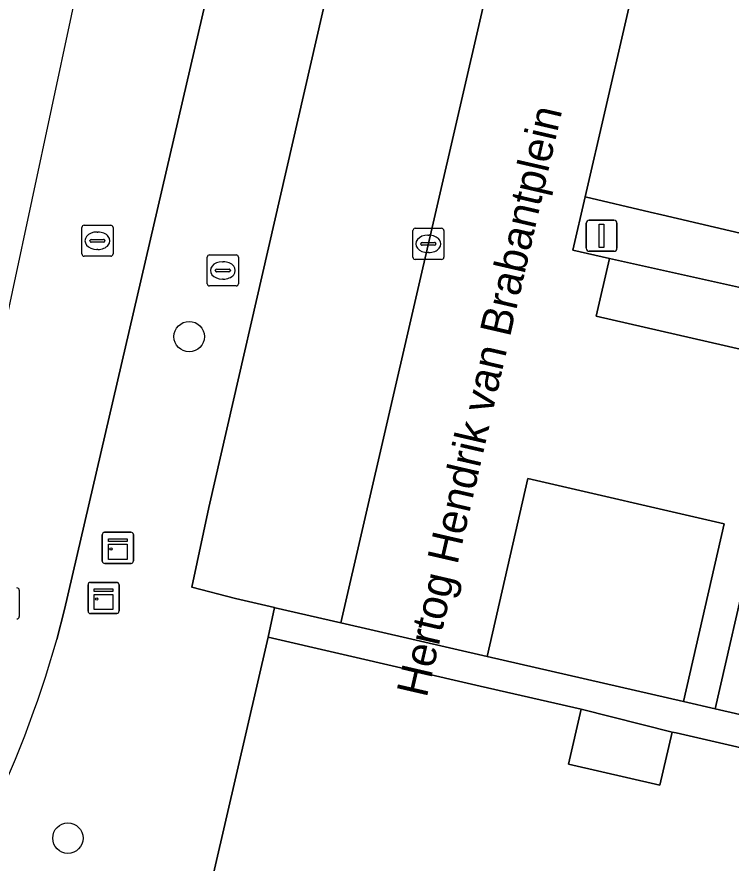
# Model space of a CAD drawing. Extents: x 161798 to 162385, y 382315 to 382833.
# Drawn here: x 161846.34 to 161869.31, y 382603.74 to 382630.93 of the extents above; entities that cross this region are included whole.
import ezdxf

# ---------------------------------------------------------------- set-up
doc = ezdxf.new("R2010")
doc.units = 0
for name, color, linetype in [('IMGEO_Boom', 7, 'Continuous'), ('IMGEO_Groenvoorziening', 7, 'Continuous'), ('IMGEO_Kast', 7, 'Continuous'), ('IMGEO_Kolk', 7, 'Continuous'), ('IMGEO_Lichtmast', 7, 'Continuous'), ('IMGEO_Openbare_ruimte_label', 7, 'Continuous'), ('IMGEO_Pand', 7, 'Continuous'), ('IMGEO_Parkeervlak_open', 7, 'Continuous'), ('IMGEO_Rijbaan_lokaal_gesloten', 7, 'Continuous'), ('IMGEO_Rijbaan_lokaal_open', 7, 'Continuous'), ('IMGEO_Rioolput', 7, 'Continuous'), ('IMGEO_Voetpad_open', 7, 'Continuous')]:
    doc.layers.add(name, color=color, linetype=linetype)

msp = doc.modelspace()

# ---------------------------------------------------------------- linework, layer by layer
at = {"layer": 'IMGEO_Boom'}
for centre in [(161851.88, 382620.655), (161847.979, 382604.538)]:
    msp.add_circle(centre, 0.489, dxfattribs=at)
at = {"layer": 'IMGEO_Groenvoorziening'}
msp.add_lwpolyline([(161866.576, 382633.64), (161864.615, 382625.149), (161866.712, 382624.656), (161867.078, 382624.57), (161873.854, 382622.982), (161875.823, 382622.52), (161880.4, 382621.447)], dxfattribs=at)
at = {"layer": 'IMGEO_Kast'}
for p, q in [((161849.086, 382613.443), (161849.086, 382614.284)), ((161849.086, 382614.284), (161849.086, 382613.443)), ((161849.161, 382614.368), (161850.002, 382614.368)), ((161850.002, 382614.368), (161849.161, 382614.368)), ((161850.086, 382614.293), (161850.086, 382613.452)), ((161850.086, 382613.452), (161850.086, 382614.293)), ((161850.011, 382613.368), (161849.17, 382613.368)), ((161849.17, 382613.368), (161850.011, 382613.368)), ((161848.626, 382611.833), (161848.626, 382612.674)), ((161848.626, 382612.674), (161848.626, 382611.833)), ((161848.701, 382612.758), (161849.542, 382612.758)), ((161849.542, 382612.758), (161848.701, 382612.758)), ((161849.626, 382612.683), (161849.626, 382611.842)), ((161849.626, 382611.842), (161849.626, 382612.683)), ((161849.551, 382611.758), (161848.71, 382611.758)), ((161848.71, 382611.758), (161849.551, 382611.758))]:
    msp.add_line(p, q, dxfattribs=at)
for points in [[(161849.281, 382614.158), (161849.881, 382614.158), (161849.881, 382614.073), (161849.281, 382614.073), (161849.281, 382614.158)], [(161849.281, 382613.983), (161849.881, 382613.983), (161849.881, 382613.494), (161849.281, 382613.494), (161849.281, 382613.983)], [(161848.821, 382612.548), (161849.421, 382612.548), (161849.421, 382612.463), (161848.821, 382612.463), (161848.821, 382612.548)], [(161848.821, 382612.373), (161849.421, 382612.373), (161849.421, 382611.884), (161848.821, 382611.884), (161848.821, 382612.373)]]:
    msp.add_lwpolyline(points, dxfattribs=at)
for centre in [(161849.365, 382613.832), (161848.905, 382612.222)]:
    msp.add_circle(centre, 0.0377, dxfattribs=at)
for centre, start, end in [((161849.164, 382614.29), 92.4484, 184.2845), ((161849.164, 382614.29), 92.4484, 184.2845), ((161850.008, 382614.29), 2.4484, 94.2845), ((161850.008, 382614.29), 2.4484, 94.2845), ((161849.164, 382613.446), 182.4484, 274.2845), ((161849.164, 382613.446), 182.4484, 274.2845), ((161850.008, 382613.446), 272.4484, 4.2845), ((161850.008, 382613.446), 272.4484, 4.2845), ((161848.704, 382612.68), 92.4484, 184.2845), ((161848.704, 382612.68), 92.4484, 184.2845), ((161849.548, 382612.68), 2.4484, 94.2845), ((161849.548, 382612.68), 2.4484, 94.2845), ((161848.704, 382611.836), 182.4484, 274.2845), ((161848.704, 382611.836), 182.4484, 274.2845), ((161849.548, 382611.836), 272.4484, 4.2845), ((161849.548, 382611.836), 272.4484, 4.2845)]:
    msp.add_arc(centre, 0.0779, start, end, dxfattribs=at)
at = {"layer": 'IMGEO_Kolk'}
for p, q in [((161859.072, 382623.21), (161859.072, 382624.062)), ((161859.147, 382624.136), (161859.999, 382624.136)), ((161860.073, 382624.062), (161860.073, 382623.21)), ((161859.56, 382623.916), (161859.585, 382623.916)), ((161859.331, 382623.63), (161859.331, 382623.642)), ((161859.769, 382623.593), (161859.371, 382623.593)), ((161859.374, 382623.679), (161859.772, 382623.679)), ((161859.815, 382623.642), (161859.815, 382623.63)), ((161859.583, 382623.356), (161859.558, 382623.356)), ((161859.999, 382623.136), (161859.147, 382623.136))]:
    msp.add_line(p, q, dxfattribs=at)
for points in [[(161859.072, 382623.21), (161859.072, 382624.062)], [(161859.147, 382624.136), (161859.999, 382624.136)], [(161860.073, 382624.062), (161860.073, 382623.21)], [(161859.999, 382623.136), (161859.147, 382623.136)]]:
    msp.add_lwpolyline(points, dxfattribs=at)
for centre, radius, start, end in [((161859.149, 382624.06), 0.0765, 91.552, 178.448), ((161859.149, 382624.06), 0.0765, 91.552, 178.448), ((161859.997, 382624.06), 0.0765, 1.552, 88.448), ((161859.997, 382624.06), 0.0765, 1.552, 88.448), ((161859.371, 382623.639), 0.0403, 85.8775, 175.7526), ((161859.368, 382623.629), 0.0366, 178.938, 274.7102), ((161859.772, 382623.636), 0.043, 264.8664, 352.4533), ((161859.776, 382623.641), 0.0386, 1.7309, 96.639), ((161859.149, 382623.212), 0.0765, 181.552, 268.448), ((161859.149, 382623.212), 0.0765, 181.552, 268.448), ((161859.997, 382623.212), 0.0765, 271.552, 358.448), ((161859.997, 382623.212), 0.0765, 271.552, 358.448)]:
    msp.add_arc(centre, radius, start, end, dxfattribs=at)
for centre, major_axis, ratio, start_param, end_param in [((161859.559, 382623.636), (-0.387, 0.002), 0.722429, 4.712389, 7.853982), ((161859.584, 382623.636), (-0.39, 0.002), 0.717154, 1.570796, 4.712389)]:
    msp.add_ellipse(centre, major_axis=major_axis, ratio=ratio, start_param=start_param, end_param=end_param, dxfattribs=at)
at = {"layer": 'IMGEO_Lichtmast'}
for p, q in [((161864.649, 382623.499), (161864.649, 382624.299)), ((161864.649, 382624.299), (161864.649, 382623.499)), ((161864.749, 382624.399), (161865.539, 382624.399)), ((161865.539, 382624.399), (161864.749, 382624.399)), ((161865.639, 382624.299), (161865.639, 382623.499)), ((161865.639, 382623.499), (161865.639, 382624.299)), ((161865.539, 382623.399), (161864.749, 382623.399)), ((161864.749, 382623.399), (161865.539, 382623.399))]:
    msp.add_line(p, q, dxfattribs=at)
msp.add_lwpolyline([(161865.069, 382624.274), (161865.219, 382624.274), (161865.219, 382623.524), (161865.069, 382623.524), (161865.069, 382624.274)], dxfattribs=at)
for centre, start, end in [((161864.749, 382624.299), 90, 180), ((161864.749, 382624.299), 90, 180), ((161865.539, 382624.299), 0, 90), ((161865.539, 382624.299), 360, 90), ((161864.749, 382623.499), 180, 270), ((161864.749, 382623.499), 180, 270), ((161865.539, 382623.499), 270, 0), ((161865.539, 382623.499), 270, 0)]:
    msp.add_arc(centre, 0.1, start, end, dxfattribs=at)
at = {"layer": 'IMGEO_Pand'}
msp.add_lwpolyline([(161880.75, 382604.884), (161878.792, 382605.334), (161867.541, 382607.918), (161867.413, 382607.947), (161867.021, 382606.239), (161864.082, 382606.914), (161864.488, 382608.68), (161861.243, 382609.426), (161854.417, 382610.994), (161848.273, 382584.466), (161874.618, 382578.415), (161876.31, 382585.719), (161876.316, 382585.744)], close=True, dxfattribs=at)
at = {"layer": 'IMGEO_Parkeervlak_open'}
for points in [[(161867.395, 382657.47), (161867.403, 382657.512), (161862.499, 382658.624), (161852.515, 382615.16), (161851.961, 382612.607), (161853.365, 382612.238), (161854.625, 382611.948), (161854.643, 382611.944), (161856.759, 382611.458)], [(161865.4, 382623.168), (161864.975, 382621.309), (161881.719, 382617.477), (161882.157, 382619.325), (161873.025, 382621.478)], [(161880.256, 382611.317), (161869.944, 382613.686), (161868.797, 382608.696), (161879.024, 382606.347)]]:
    msp.add_lwpolyline(points, close=True, dxfattribs=at)
at = {"layer": 'IMGEO_Rijbaan_lokaal_gesloten'}
msp.add_lwpolyline([(161847.621, 382610.917), (161847.865, 382611.889), (161858.977, 382659.682), (161854.413, 382660.541), (161842.384, 382604.352), (161834.027, 382596.507)], dxfattribs=at)
msp.add_arc((161812.716, 382620.857), 36.292, 323.5737, 344.1044, dxfattribs=at)
at = {"layer": 'IMGEO_Rijbaan_lokaal_open'}
msp.add_lwpolyline([(161864.975, 382621.309), (161865.4, 382623.168), (161864.218, 382623.43), (161864.615, 382625.149), (161866.576, 382633.64), (161871.857, 382656.486), (161867.395, 382657.47), (161856.759, 382611.458), (161861.462, 382610.378), (161862.775, 382616.091), (161869.085, 382614.642), (161867.774, 382608.931), (161868.797, 382608.696), (161869.944, 382613.686), (161880.256, 382611.317), (161880.309, 382611.531), (161881.719, 382617.477)], close=True, dxfattribs=at)
at = {"layer": 'IMGEO_Rioolput'}
for p, q in [((161848.504, 382624.237), (161849.356, 382624.237)), ((161848.429, 382623.311), (161848.429, 382624.163)), ((161848.917, 382624.017), (161848.942, 382624.017)), ((161849.43, 382624.163), (161849.43, 382623.311)), ((161848.688, 382623.731), (161848.688, 382623.743)), ((161849.126, 382623.694), (161848.728, 382623.694)), ((161848.731, 382623.78), (161849.129, 382623.78)), ((161849.172, 382623.743), (161849.172, 382623.731)), ((161848.94, 382623.457), (161848.915, 382623.457)), ((161849.356, 382623.237), (161848.504, 382623.237)), ((161852.462, 382622.357), (161852.462, 382623.209)), ((161852.537, 382623.283), (161853.389, 382623.283)), ((161853.463, 382623.209), (161853.463, 382622.357)), ((161852.95, 382623.063), (161852.975, 382623.063)), ((161852.721, 382622.777), (161852.721, 382622.789)), ((161853.159, 382622.74), (161852.761, 382622.74)), ((161852.764, 382622.826), (161853.162, 382622.826)), ((161853.205, 382622.789), (161853.205, 382622.777)), ((161852.973, 382622.503), (161852.948, 382622.503)), ((161853.389, 382622.283), (161852.537, 382622.283)), ((161846.413, 382612.508), (161846.413, 382611.656))]:
    msp.add_line(p, q, dxfattribs=at)
for points in [[(161848.504, 382624.237), (161849.356, 382624.237)], [(161848.429, 382623.311), (161848.429, 382624.163)], [(161849.43, 382624.163), (161849.43, 382623.311)], [(161849.356, 382623.237), (161848.504, 382623.237)], [(161852.462, 382622.357), (161852.462, 382623.209)], [(161852.537, 382623.283), (161853.389, 382623.283)], [(161853.463, 382623.209), (161853.463, 382622.357)], [(161853.389, 382622.283), (161852.537, 382622.283)], [(161846.413, 382612.508), (161846.413, 382611.656)]]:
    msp.add_lwpolyline(points, dxfattribs=at)
for centre, radius, start, end in [((161848.506, 382624.161), 0.0765, 91.552, 178.448), ((161848.506, 382624.161), 0.0765, 91.552, 178.448), ((161849.354, 382624.161), 0.0765, 1.552, 88.448), ((161849.354, 382624.161), 0.0765, 1.552, 88.448), ((161848.728, 382623.74), 0.0403, 85.8775, 175.7526), ((161848.725, 382623.73), 0.0366, 178.938, 274.7102), ((161849.129, 382623.737), 0.043, 264.8664, 352.4533), ((161849.133, 382623.742), 0.0386, 1.7309, 96.639), ((161848.506, 382623.313), 0.0765, 181.552, 268.448), ((161848.506, 382623.313), 0.0765, 181.552, 268.448), ((161849.354, 382623.313), 0.0765, 271.552, 358.448), ((161849.354, 382623.313), 0.0765, 271.552, 358.448), ((161852.539, 382623.207), 0.0765, 91.552, 178.448), ((161852.539, 382623.207), 0.0765, 91.552, 178.448), ((161853.387, 382623.207), 0.0765, 1.552, 88.448), ((161853.387, 382623.207), 0.0765, 1.552, 88.448), ((161852.761, 382622.786), 0.0403, 85.8775, 175.7526), ((161852.758, 382622.776), 0.0366, 178.938, 274.7102), ((161853.162, 382622.783), 0.043, 264.8664, 352.4533), ((161853.166, 382622.788), 0.0386, 1.7309, 96.639), ((161852.539, 382622.359), 0.0765, 181.552, 268.448), ((161852.539, 382622.359), 0.0765, 181.552, 268.448), ((161853.387, 382622.359), 0.0765, 271.552, 358.448), ((161853.387, 382622.359), 0.0765, 271.552, 358.448), ((161846.337, 382612.506), 0.0765, 1.552, 88.448), ((161846.337, 382612.506), 0.0765, 1.552, 88.448), ((161846.337, 382611.658), 0.0765, 271.552, 358.448), ((161846.337, 382611.658), 0.0765, 271.552, 358.448)]:
    msp.add_arc(centre, radius, start, end, dxfattribs=at)
for centre, major_axis, ratio, start_param, end_param in [((161848.916, 382623.737), (-0.387, 0.002), 0.722429, 4.712389, 7.853982), ((161848.941, 382623.737), (-0.39, 0.002), 0.717154, 1.570796, 4.712389), ((161852.949, 382622.783), (-0.387, 0.002), 0.722429, 4.712389, 7.853982), ((161852.974, 382622.783), (-0.39, 0.002), 0.717154, 1.570796, 4.712389)]:
    msp.add_ellipse(centre, major_axis=major_axis, ratio=ratio, start_param=start_param, end_param=end_param, dxfattribs=at)
at = {"layer": 'IMGEO_Voetpad_open'}
for points in [[(161864.218, 382683.068), (161865.926, 382682.68), (161863.729, 382672.623), (161862.058, 382673.008), (161859.058, 382659.932), (161859.036, 382659.936), (161858.977, 382659.682), (161847.865, 382611.889), (161847.621, 382610.917)], [(161852.515, 382615.16), (161862.499, 382658.624), (161865.693, 382672.206)], [(161880.4, 382621.447), (161875.823, 382622.52), (161873.854, 382622.982), (161867.078, 382624.57), (161866.712, 382624.656), (161864.615, 382625.149), (161864.218, 382623.43), (161865.4, 382623.168), (161873.025, 382621.478), (161882.157, 382619.325), (161881.719, 382617.477), (161880.309, 382611.531), (161880.256, 382611.317), (161879.024, 382606.347), (161878.792, 382605.334), (161880.75, 382604.884), (161876.316, 382585.744)], [(161825.439, 382553.816), (161828.257, 382544.094), (161830.293, 382544.807), (161829.008, 382548.459), (161834.995, 382548.753), (161833.792, 382552.574), (161833.538, 382552.632), (161833.632, 382553.034), (161835.475, 382561.365), (161835.984, 382561.246), (161836.696, 382561.08), (161839.076, 382560.524), (161840.942, 382568.825), (161841.435, 382568.714), (161844.52, 382568.021), (161846.398, 382576.246), (161848.273, 382584.466), (161854.417, 382610.994), (161854.625, 382611.948), (161853.365, 382612.238), (161851.961, 382612.607), (161852.515, 382615.16)]]:
    msp.add_lwpolyline(points, dxfattribs=at)
for points in [[(161869.085, 382614.642), (161862.775, 382616.091), (161861.462, 382610.378), (161867.774, 382608.931)], [(161854.643, 382611.944), (161854.625, 382611.948), (161854.417, 382610.994), (161861.243, 382609.426), (161864.488, 382608.68), (161867.413, 382607.947), (161867.541, 382607.918), (161878.792, 382605.334), (161879.024, 382606.347), (161868.797, 382608.696), (161867.774, 382608.931), (161861.462, 382610.378), (161856.759, 382611.458)], [(161864.488, 382608.68), (161864.082, 382606.914), (161867.021, 382606.239), (161867.413, 382607.947)]]:
    msp.add_lwpolyline(points, close=True, dxfattribs=at)
msp.add_arc((161812.716, 382620.857), 36.292, 323.5737, 344.1044, dxfattribs=at)

# ---------------------------------------------------------------- texts
at = {"layer": 'IMGEO_Openbare_ruimte_label'}
msp.add_text('Hertog Hendrik van Brabantplein', height=1, rotation=76.9925, dxfattribs=at).set_placement((161859.517, 382609.026))

doc.saveas('drawing.dxf')
